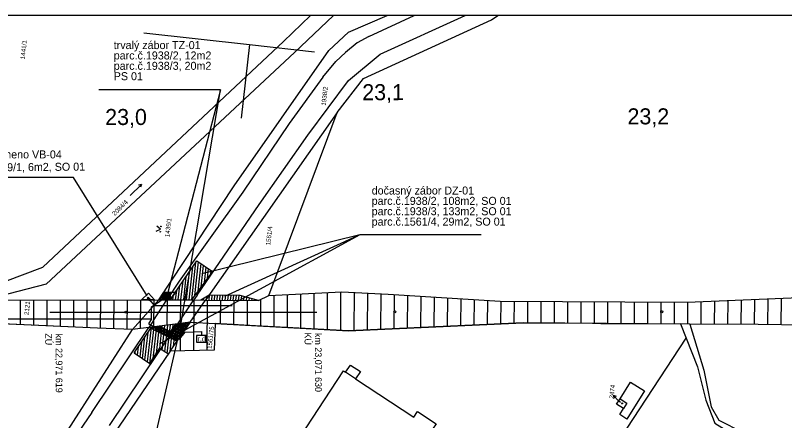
# Model space of a CAD drawing. Extents: x -794765 to -785424, y -1118958 to -1108731.
# Drawn here: x -794556.2 to -794268, y -1110577.7 to -1110426 of the extents above; entities that cross this region are included whole.
import ezdxf

# ---------------------------------------------------------------- set-up
doc = ezdxf.new("R2010")
doc.units = 0
for name, color, linetype in [('Level 66', 7, 'Continuous'), ('Level 71', 7, 'Continuous'), ('Level 73', 7, 'Continuous'), ('Level 75', 7, 'Continuous'), ('Level 76', 7, 'Continuous'), ('Level 77', 7, 'Continuous'), ('Level 78', 7, 'Continuous'), ('Level 79', 7, 'Continuous'), ('Level 80', 7, 'Continuous'), ('Vrstva 1', 7, 'Continuous'), ('Vrstva 53', 7, 'Continuous')]:
    doc.layers.add(name, color=color, linetype=linetype)

msp = doc.modelspace()

# ---------------------------------------------------------------- linework, layer by layer
at = {"layer": 'Level 66'}
for p, q in [((-794513.23, -1110493.46), (-794508.96, -1110489.25)), ((-794508.96, -1110489.25), (-794510.01, -1110489.58)), ((-794508.96, -1110489.25), (-794509.31, -1110490.29))]:
    msp.add_line(p, q, dxfattribs=at)
msp.add_lwpolyline([(-794503.38, -1110506.83), (-794501.77, -1110506), (-794503.15, -1110504.84)], dxfattribs=at)
for centre in [(-794501.66, -1110505.01), (-794501.88, -1110507)]:
    msp.add_circle(centre, 0.1, dxfattribs=at)
at = {"layer": 'Level 71'}
msp.add_line((-793863.95, -1110425.97), (-794764.72, -1110425.97), dxfattribs=at)
at = {"layer": 'Level 75'}
for p, q in [((-794435.64, -1110462.33), (-794484.92, -1110532.56)), ((-794461.25, -1110530.91), (-794435.64, -1110462.33)), ((-794563.75, -1110532.65), (-794502.43, -1110532.44)), ((-794502.43, -1110532.44), (-794499.4, -1110532.46)), ((-794499.4, -1110532.46), (-794489.27, -1110532.53)), ((-794490.73, -1110540.85), (-794484.92, -1110532.56)), ((-794489.27, -1110532.53), (-794484.92, -1110532.56)), ((-794498.16, -1110551.76), (-794490.73, -1110540.85)), ((-794490.73, -1110540.85), (-794495.27, -1110541.44)), ((-794490.73, -1110540.85), (-794481.35, -1110541.37)), ((-794506.24, -1110542.85), (-794512.24, -1110543.62)), ((-794495.27, -1110541.44), (-794506.24, -1110542.85)), ((-794307, -1110541.53), (-794304.9, -1110546.83)), ((-794303.51, -1110541.56), (-794307, -1110541.53)), ((-794382.83, -1110665.46), (-794304.9, -1110546.83))]:
    msp.add_line(p, q, dxfattribs=at)
for points in [[(-794569.05, -1110532.66), (-794566.83, -1110528.14), (-794545.92, -1110520.3), (-794455.77, -1110435.78), (-794445.68, -1110425.97)], [(-794437.06, -1110425.97), (-794451.66, -1110439.85), (-794544.58, -1110526.66), (-794562.65, -1110531.19), (-794563.75, -1110532.65)], [(-794438.77, -1110439.12), (-794431.4, -1110432.22), (-794416.91, -1110425.97)], [(-794435.64, -1110462.33), (-794425.72, -1110449.58), (-794377.85, -1110427.65), (-794375.39, -1110425.97)], [(-794502.43, -1110532.44), (-794474.19, -1110489.74), (-794438.77, -1110439.12)], [(-794484.92, -1110532.56), (-794465.05, -1110532.71), (-794461.25, -1110530.91)], [(-794461.25, -1110530.91), (-794433.94, -1110529.51), (-794416.47, -1110530.42), (-794374.52, -1110532.93), (-794304.55, -1110533.4), (-794259.63, -1110531.53), (-794179.14, -1110530.95), (-794108.47, -1110532.75), (-794104.14, -1110532.79)], [(-794639.83, -1110726.74), (-794626.42, -1110708.17), (-794618.82, -1110702.4), (-794541.78, -1110589.48), (-794512.24, -1110543.62)], [(-794512.24, -1110543.62), (-794525.37, -1110543.07), (-794563.98, -1110541.29), (-794564.28, -1110541.29)], [(-794481.35, -1110541.37), (-794481.77, -1110551.37), (-794498.16, -1110551.76)], [(-794481.35, -1110541.37), (-794431.43, -1110544.09), (-794365.92, -1110541.06), (-794340, -1110541.27), (-794336.92, -1110541.29), (-794307, -1110541.53)], [(-794103.63, -1110542.16), (-794108.46, -1110542.18), (-794182.02, -1110543.07), (-794277.92, -1110541.77), (-794303.51, -1110541.56)], [(-794303.51, -1110541.56), (-794298.33, -1110558.86), (-794295.52, -1110572.59), (-794292.66, -1110577.57), (-794283.75, -1110582), (-794250.19, -1110588.78), (-794232.47, -1110589.11), (-794190.29, -1110595.64), (-794168.42, -1110600.62), (-794159.77, -1110604.9)], [(-794304.9, -1110546.83), (-794300.65, -1110557.55), (-794297.56, -1110570.01), (-794294.21, -1110578.7), (-794285.26, -1110584.18), (-794250.99, -1110590.67), (-794233.64, -1110591.68), (-794191.07, -1110598.44), (-794159.77, -1110604.9)], [(-794498.16, -1110551.76), (-794529.99, -1110598.46), (-794531.8, -1110601.13)], [(-794481.28, -1110658.62), (-794477.38, -1110652.72), (-794489.45, -1110644.78), (-794433.25, -1110559.1), (-794432.45, -1110559.62), (-794430.68, -1110556.89), (-794426.92, -1110559.28), (-794428.75, -1110562.06), (-794406.87, -1110576.43), (-794405.48, -1110574.3), (-794398.59, -1110578.92), (-794399.94, -1110580.98), (-794360.02, -1110607.21), (-794416.32, -1110692.87), (-794428.4, -1110684.94), (-794432.27, -1110690.83)], [(-794328.37, -1110573.19), (-794330.96, -1110571.57), (-794329.68, -1110569.51), (-794325.79, -1110563.26), (-794320.49, -1110566.59), (-794327.15, -1110577.13), (-794329.76, -1110575.48), (-794328.37, -1110573.19)]]:
    msp.add_lwpolyline(points, dxfattribs=at)
at = {"layer": 'Level 77'}
for p, q in [((-794423.73, -1110433.83), (-794406.83, -1110425.97)), ((-794419.5, -1110440.48), (-794387.65, -1110425.97)), ((-794423.73, -1110433.83), (-794428.14, -1110436.28)), ((-794428.14, -1110436.28), (-794432.53, -1110439.86)), ((-794432.53, -1110439.86), (-794436.19, -1110443.25)), ((-794431.42, -1110450.32), (-794419.5, -1110440.48)), ((-794440.95, -1110449.05), (-794436.19, -1110443.25)), ((-794440.95, -1110449.05), (-794453.58, -1110466.48)), ((-794446.66, -1110470.8), (-794431.42, -1110450.32)), ((-794453.58, -1110466.48), (-794470.96, -1110492.11)), ((-794464.86, -1110496.76), (-794446.66, -1110470.8)), ((-794470.96, -1110492.11), (-794494.86, -1110525.52)), ((-794488.07, -1110530.73), (-794464.86, -1110496.76)), ((-794494.86, -1110525.52), (-794499.4, -1110532.46)), ((-794488.07, -1110530.73), (-794489.27, -1110532.53)), ((-794502.43, -1110532.44), (-794512.24, -1110543.62)), ((-794504.46, -1110540.19), (-794499.4, -1110532.46)), ((-794495.27, -1110541.44), (-794489.27, -1110532.53)), ((-794504.46, -1110540.19), (-794506.24, -1110542.85)), ((-794527.59, -1110574.62), (-794506.24, -1110542.85)), ((-794520.95, -1110579.5), (-794496.39, -1110543.1)), ((-794496.39, -1110543.1), (-794495.27, -1110541.44)), ((-794428.75, -1110562.06), (-794432.45, -1110559.62)), ((-794329.68, -1110569.51), (-794327.09, -1110571.12)), ((-794327.09, -1110571.12), (-794328.37, -1110573.19)), ((-794527.59, -1110574.62), (-794548, -1110604.53))]:
    msp.add_line(p, q, dxfattribs=at)
at = {"layer": 'Level 78'}
for p, q in [((-794459.29, -1110542.56), (-794459.21, -1110530.81)), ((-794454.29, -1110542.84), (-794454.21, -1110530.55)), ((-794449.29, -1110543.11), (-794449.2, -1110530.29)), ((-794444.29, -1110543.38), (-794444.2, -1110530.04)), ((-794439.29, -1110543.66), (-794439.2, -1110529.78)), ((-794434.29, -1110543.93), (-794434.2, -1110529.52)), ((-794429.29, -1110543.99), (-794429.2, -1110529.76)), ((-794424.29, -1110543.76), (-794424.2, -1110530.02)), ((-794419.29, -1110543.53), (-794419.2, -1110530.28)), ((-794414.29, -1110543.3), (-794414.21, -1110530.56)), ((-794409.29, -1110543.06), (-794409.21, -1110530.86)), ((-794404.29, -1110542.83), (-794404.21, -1110531.16)), ((-794399.28, -1110542.6), (-794399.21, -1110531.45)), ((-794394.28, -1110542.37), (-794394.21, -1110531.75)), ((-794389.28, -1110542.14), (-794389.21, -1110532.05)), ((-794274.28, -1110541.82), (-794274.21, -1110532.14)), ((-794269.28, -1110541.89), (-794269.21, -1110531.93)), ((-794554.28, -1110541.74), (-794554.22, -1110532.62)), ((-794549.28, -1110541.97), (-794549.22, -1110532.6)), ((-794544.28, -1110542.2), (-794544.22, -1110532.58)), ((-794539.29, -1110542.43), (-794539.22, -1110532.57)), ((-794534.29, -1110542.66), (-794534.22, -1110532.55)), ((-794529.29, -1110542.89), (-794529.22, -1110532.53)), ((-794524.29, -1110543.11), (-794524.22, -1110532.51)), ((-794519.29, -1110543.32), (-794519.22, -1110532.5)), ((-794514.29, -1110543.53), (-794514.22, -1110532.48)), ((-794509.29, -1110543.24), (-794509.22, -1110532.46)), ((-794504.29, -1110542.6), (-794504.22, -1110532.44)), ((-794499.28, -1110541.96), (-794499.22, -1110532.46)), ((-794494.28, -1110541.31), (-794494.22, -1110532.5)), ((-794489.35, -1110551.55), (-794489.22, -1110532.53)), ((-794484.34, -1110551.43), (-794484.22, -1110532.57)), ((-794479.28, -1110541.48), (-794479.22, -1110532.61)), ((-794474.28, -1110541.75), (-794474.22, -1110532.64)), ((-794469.28, -1110542.02), (-794469.22, -1110532.68)), ((-794464.28, -1110542.29), (-794464.22, -1110532.32)), ((-794384.28, -1110541.91), (-794384.22, -1110532.35)), ((-794379.28, -1110541.68), (-794379.22, -1110532.65)), ((-794374.28, -1110541.45), (-794374.22, -1110532.93)), ((-794369.27, -1110541.22), (-794369.22, -1110532.96)), ((-794364.27, -1110541.08), (-794364.22, -1110533)), ((-794359.27, -1110541.12), (-794359.22, -1110533.03)), ((-794354.27, -1110541.16), (-794354.22, -1110533.07)), ((-794349.27, -1110541.2), (-794349.22, -1110533.1)), ((-794344.27, -1110541.23), (-794344.22, -1110533.13)), ((-794339.27, -1110541.27), (-794339.22, -1110533.17)), ((-794334.27, -1110541.31), (-794334.22, -1110533.2)), ((-794329.27, -1110541.35), (-794329.22, -1110533.23)), ((-794324.27, -1110541.39), (-794324.22, -1110533.27)), ((-794319.28, -1110541.43), (-794319.22, -1110533.3)), ((-794314.28, -1110541.47), (-794314.22, -1110533.34)), ((-794309.28, -1110541.51), (-794309.22, -1110533.37)), ((-794304.28, -1110541.55), (-794304.22, -1110533.39)), ((-794299.28, -1110541.59), (-794299.22, -1110533.18)), ((-794294.28, -1110541.63), (-794294.22, -1110532.97)), ((-794289.28, -1110541.68), (-794289.22, -1110532.76)), ((-794284.28, -1110541.72), (-794284.22, -1110532.55)), ((-794279.28, -1110541.76), (-794279.21, -1110532.34)), ((-794494.35, -1110551.67), (-794494.31, -1110546.11))]:
    msp.add_line(p, q, dxfattribs=at)
at = {"layer": 'Level 79'}
msp.add_circle((-794328.92, -1110571.29), 0.175, dxfattribs=at)
at = {"layer": 'Level 80'}
for p, q in [((-794330.11, -1110570.38), (-794332.22, -1110568.24)), ((-794332.22, -1110568.24), (-794331.16, -1110568.61)), ((-794332.22, -1110568.24), (-794331.87, -1110569.31)), ((-794329.53, -1110570.98), (-794330.11, -1110570.38))]:
    msp.add_line(p, q, dxfattribs=at)
at = {"layer": 'Vrstva 1'}
for p, q in [((-794508.04, -1110432.46), (-794468.5, -1110436.88)), ((-794468.5, -1110436.88), (-794471.59, -1110464.49)), ((-794468.5, -1110436.88), (-794444.13, -1110439.6)), ((-794479.37, -1110453.88), (-794524.86, -1110453.88)), ((-794479.37, -1110453.88), (-794499.23, -1110530.2)), ((-794494.38, -1110542.53), (-794479.37, -1110453.88)), ((-794534.44, -1110486.62), (-794579.93, -1110486.62)), ((-794427.16, -1110508.13), (-794502.31, -1110549.13)), ((-794427.16, -1110508.13), (-794486.33, -1110522.74)), ((-794427.16, -1110508.13), (-794477.86, -1110531.23)), ((-794381.68, -1110508.13), (-794427.16, -1110508.13)), ((-794498.16, -1110532.47), (-794488.19, -1110517.86)), ((-794488.19, -1110517.86), (-794482.34, -1110521.82)), ((-794491.12, -1110532.52), (-794489.74, -1110520.12)), ((-794490.11, -1110532.49), (-794488.54, -1110518.36)), ((-794488.93, -1110530.86), (-794487.52, -1110518.31)), ((-794487.74, -1110529.23), (-794486.59, -1110518.94)), ((-794486.55, -1110527.6), (-794485.65, -1110519.58)), ((-794485.36, -1110525.97), (-794484.72, -1110520.21)), ((-794492.13, -1110532.51), (-794490.94, -1110521.89)), ((-794482.34, -1110521.82), (-794490.14, -1110532.52)), ((-794484.17, -1110524.34), (-794483.78, -1110520.84)), ((-794482.98, -1110522.71), (-794482.85, -1110521.48)), ((-794494.14, -1110532.49), (-794493.35, -1110525.41)), ((-794493.13, -1110532.5), (-794492.15, -1110523.65)), ((-794496.15, -1110532.48), (-794495.75, -1110528.93)), ((-794495.15, -1110532.49), (-794494.55, -1110527.17)), ((-794506.33, -1110530.03), (-794508.88, -1110532.46)), ((-794506.37, -1110531.45), (-794506.84, -1110531.9)), ((-794506.37, -1110531.45), (-794506.84, -1110531.9)), ((-794506.84, -1110531.9), (-794506.02, -1110532.77)), ((-794506.84, -1110531.9), (-794506.02, -1110532.77)), ((-794506.74, -1110531.8), (-794506.05, -1110532.52)), ((-794506.74, -1110531.8), (-794506.05, -1110532.52)), ((-794505.79, -1110532.27), (-794506.48, -1110531.55)), ((-794506.48, -1110531.55), (-794505.79, -1110532.27)), ((-794505.54, -1110532.32), (-794506.37, -1110531.45)), ((-794506.37, -1110531.45), (-794505.54, -1110532.32)), ((-794504.03, -1110532.44), (-794506.33, -1110530.03)), ((-794505.15, -1110535.12), (-794498.51, -1110530.57)), ((-794502.23, -1110532.44), (-794502.19, -1110532.07)), ((-794501.73, -1110532.44), (-794501.59, -1110531.16)), ((-794501.23, -1110532.45), (-794500.98, -1110530.24)), ((-794500.73, -1110532.45), (-794500.4, -1110529.56)), ((-794500.22, -1110532.45), (-794499.9, -1110529.56)), ((-794499.72, -1110532.46), (-794499.4, -1110529.56)), ((-794499.22, -1110532.46), (-794498.89, -1110529.57)), ((-794498.71, -1110532.46), (-794498.39, -1110529.57)), ((-794498.21, -1110532.47), (-794497.89, -1110529.57)), ((-794497.16, -1110532.47), (-794496.96, -1110530.7)), ((-794483.58, -1110530.73), (-794486.65, -1110532.55)), ((-794485.65, -1110532.56), (-794485.58, -1110531.91)), ((-794484.64, -1110532.57), (-794484.5, -1110531.28)), ((-794483.64, -1110532.57), (-794483.43, -1110530.74)), ((-794471.94, -1110530.85), (-794483.58, -1110530.73)), ((-794482.63, -1110532.58), (-794482.43, -1110530.75)), ((-794481.63, -1110532.59), (-794481.42, -1110530.76)), ((-794480.62, -1110532.6), (-794480.42, -1110530.76)), ((-794479.62, -1110532.6), (-794479.41, -1110530.77)), ((-794478.61, -1110532.61), (-794478.41, -1110530.78)), ((-794477.61, -1110532.62), (-794477.4, -1110530.79)), ((-794476.6, -1110532.63), (-794476.4, -1110530.8)), ((-794475.6, -1110532.63), (-794475.39, -1110530.81)), ((-794474.59, -1110532.64), (-794474.39, -1110530.82)), ((-794473.58, -1110532.65), (-794473.38, -1110530.83)), ((-794472.58, -1110532.66), (-794472.38, -1110530.84)), ((-794465.05, -1110532.71), (-794471.94, -1110530.85)), ((-794471.57, -1110532.66), (-794471.39, -1110531)), ((-794470.57, -1110532.67), (-794470.41, -1110531.26)), ((-794469.56, -1110532.68), (-794469.43, -1110531.53)), ((-794468.56, -1110532.69), (-794468.46, -1110531.79)), ((-794467.55, -1110532.69), (-794467.48, -1110532.05)), ((-794507.21, -1110532.46), (-794507.21, -1110532.46)), ((-794506.05, -1110532.52), (-794505.79, -1110532.27)), ((-794506.05, -1110532.52), (-794505.79, -1110532.27)), ((-794506.02, -1110532.77), (-794505.54, -1110532.32)), ((-794506.02, -1110532.77), (-794505.54, -1110532.32)), ((-794503.88, -1110534.71), (-794505.78, -1110532.54)), ((-794505.18, -1110539.61), (-794505.15, -1110535.12)), ((-794475.02, -1110534.68), (-794503.88, -1110534.71)), ((-794502.43, -1110532.44), (-794499.4, -1110532.46)), ((-794466.55, -1110532.7), (-794466.5, -1110532.32)), ((-794465.54, -1110532.71), (-794465.53, -1110532.58)), ((-794575.12, -1110539.63), (-794527.51, -1110539.57)), ((-794527.51, -1110539.57), (-794505.18, -1110539.61)), ((-794505.18, -1110539.61), (-794506.34, -1110541.45)), ((-794490.73, -1110540.85), (-794495.27, -1110541.44)), ((-794491.23, -1110541.59), (-794491.16, -1110540.91)), ((-794511.66, -1110552.33), (-794505.19, -1110542.72)), ((-794506.68, -1110555.72), (-794505.24, -1110542.78)), ((-794506.34, -1110541.45), (-794497.72, -1110545.73)), ((-794505.97, -1110542.81), (-794495.54, -1110547.91)), ((-794505.75, -1110556.35), (-794504.21, -1110542.59)), ((-794505.56, -1110543.01), (-794505.53, -1110542.75)), ((-794505.08, -1110543.24), (-794505.02, -1110542.69)), ((-794504.6, -1110543.48), (-794504.51, -1110542.62)), ((-794504.53, -1110554.46), (-794503.19, -1110542.46)), ((-794504.13, -1110543.71), (-794504, -1110542.56)), ((-794503.65, -1110543.94), (-794503.49, -1110542.49)), ((-794503.31, -1110552.56), (-794502.17, -1110542.33)), ((-794503.17, -1110544.18), (-794502.98, -1110542.43)), ((-794502.7, -1110544.41), (-794502.47, -1110542.36)), ((-794502.36, -1110542.35), (-794498.09, -1110544.43)), ((-794502.22, -1110544.64), (-794501.98, -1110542.53)), ((-794502.1, -1110550.75), (-794501.15, -1110542.2)), ((-794501.74, -1110544.88), (-794501.51, -1110542.77)), ((-794501.26, -1110545.11), (-794501.03, -1110543)), ((-794501.16, -1110551.34), (-794500.13, -1110542.07)), ((-794500.79, -1110545.34), (-794500.55, -1110543.23)), ((-794500.31, -1110545.58), (-794500.07, -1110543.47)), ((-794500.22, -1110551.94), (-794499.11, -1110541.94)), ((-794499.83, -1110545.81), (-794499.6, -1110543.7)), ((-794499.28, -1110552.53), (-794498.08, -1110541.81)), ((-794496.05, -1110541.54), (-794498.09, -1110544.43)), ((-794497.72, -1110545.73), (-794496.01, -1110543.22)), ((-794497.61, -1110544.67), (-794497.49, -1110543.59)), ((-794497.24, -1110543.23), (-794497.06, -1110541.67)), ((-794497.14, -1110544.9), (-794496.89, -1110542.74)), ((-794496.66, -1110545.13), (-794496.3, -1110541.9)), ((-794496.18, -1110545.37), (-794495.75, -1110541.51)), ((-794495.7, -1110545.6), (-794495.24, -1110541.44)), ((-794495.23, -1110545.83), (-794494.73, -1110541.37)), ((-794494.75, -1110546.06), (-794494.22, -1110541.31)), ((-794494.24, -1110546.01), (-794493.71, -1110541.24)), ((-794493.64, -1110545.12), (-794493.2, -1110541.17)), ((-794493.04, -1110544.24), (-794492.69, -1110541.11)), ((-794492.44, -1110543.36), (-794492.18, -1110541.04)), ((-794491.83, -1110542.48), (-794491.67, -1110540.97)), ((-794508.55, -1110554.44), (-794507.65, -1110546.37)), ((-794507.62, -1110555.08), (-794506.44, -1110544.58)), ((-794499.36, -1110546.04), (-794499.12, -1110543.93)), ((-794498.88, -1110546.28), (-794498.64, -1110544.16)), ((-794498.4, -1110546.51), (-794498.17, -1110544.4)), ((-794498.2, -1110551.81), (-794497.41, -1110544.77)), ((-794498.09, -1110544.43), (-794494.4, -1110546.24)), ((-794498.09, -1110544.43), (-794498.09, -1110544.43)), ((-794497.93, -1110546.74), (-794497.69, -1110544.63)), ((-794497.72, -1110545.73), (-794494.75, -1110547.18)), ((-794497.45, -1110546.98), (-794497.21, -1110544.86)), ((-794496.99, -1110550.05), (-794496.45, -1110545.23)), ((-794496.97, -1110547.21), (-794496.73, -1110545.1)), ((-794496.49, -1110547.44), (-794496.26, -1110545.33)), ((-794496.02, -1110547.68), (-794495.78, -1110545.56)), ((-794495.79, -1110548.28), (-794495.5, -1110545.7)), ((-794495.54, -1110547.91), (-794495.3, -1110545.79)), ((-794494.94, -1110547.03), (-794494.83, -1110546.03)), ((-794494.75, -1110547.18), (-794492.53, -1110544.65)), ((-794494.59, -1110546.51), (-794494.55, -1110546.16)), ((-794492.53, -1110544.65), (-794486.51, -1110544.37)), ((-794484.71, -1110545.84), (-794488.31, -1110545.85)), ((-794488.31, -1110545.85), (-794488.31, -1110548.36)), ((-794486.51, -1110544.37), (-794486.51, -1110545.85)), ((-794484.71, -1110548.34), (-794484.71, -1110545.84)), ((-794509.49, -1110553.81), (-794508.86, -1110548.17)), ((-794506.01, -1110593.59), (-794495.26, -1110547.22)), ((-794488.31, -1110548.36), (-794484.71, -1110548.34)), ((-794511.66, -1110552.33), (-794505.75, -1110556.35)), ((-794511.36, -1110552.53), (-794511.27, -1110551.76)), ((-794510.42, -1110553.17), (-794510.06, -1110549.96)), ((-794505.75, -1110556.35), (-794502.13, -1110550.73)), ((-794498.87, -1110552.79), (-794502.13, -1110550.73)), ((-794498.16, -1110551.76), (-794498.16, -1110551.76))]:
    msp.add_line(p, q, dxfattribs=at)
for points in [[(-794506.86, -1110530.99), (-794534.44, -1110486.62)], [(-794543.21, -1110537.14), (-794522.01, -1110537.12), (-794518.01, -1110537.12), (-794502.41, -1110537.1), (-794491.62, -1110537.1), (-794443.19, -1110537.05)]]:
    msp.add_lwpolyline(points, dxfattribs=at)
for points in [[(-794508.88, -1110532.46), (-794506.33, -1110530.03), (-794504.03, -1110532.44)], [(-794502.43, -1110532.44), (-794500.53, -1110529.56), (-794496.2, -1110529.58), (-794498.16, -1110532.47), (-794499.4, -1110532.46)], [(-794498.09, -1110544.43), (-794496.05, -1110541.54), (-794495.27, -1110541.44), (-794490.73, -1110540.85), (-794494.4, -1110546.24)], [(-794505.97, -1110542.81), (-794495.54, -1110547.91), (-794494.4, -1110546.24), (-794498.09, -1110544.43), (-794502.36, -1110542.35)]]:
    msp.add_lwpolyline(points, close=True, dxfattribs=at)
for centre in [(-794514.82, -1110537.12), (-794414.07, -1110537.02), (-794314.07, -1110536.93)]:
    msp.add_circle(centre, 0.375, dxfattribs=at)
at = {"layer": 'Vrstva 53'}
for points in [[(-794502.43, -1110532.44), (-794489.27, -1110532.53), (-794484.92, -1110532.56), (-794465.05, -1110532.71), (-794461.25, -1110530.91), (-794433.94, -1110529.51), (-794416.47, -1110530.42), (-794374.52, -1110532.93), (-794304.55, -1110533.4), (-794259.63, -1110531.53), (-794179.14, -1110530.95), (-794108.47, -1110532.75), (-794084.53, -1110532.8), (-794010.09, -1110532.85), (-793996.56, -1110532.76), (-793981.76, -1110532.68), (-793975.51, -1110532.65), (-793967.39, -1110532.61), (-793910.94, -1110532.3), (-793878.1, -1110531.77), (-793873.87, -1110531.7), (-793863.95, -1110531.55)], [(-794525.37, -1110543.07), (-794564.28, -1110541.29), (-794564.28, -1110541.29), (-794564.17, -1110539.4), (-794565.51, -1110539.39), (-794565.52, -1110535.1), (-794563.9, -1110535.12), (-794563.75, -1110532.65), (-794502.43, -1110532.44)], [(-793863.95, -1110540.92), (-793872.21, -1110540.79), (-793877.49, -1110541.02), (-793973.24, -1110541.53), (-793978.2, -1110541.55), (-793980.91, -1110541.57), (-793989.37, -1110541.63), (-794005.25, -1110541.75), (-794103.63, -1110542.16), (-794108.46, -1110542.18), (-794182.02, -1110543.07), (-794277.92, -1110541.77), (-794303.51, -1110541.56), (-794365.92, -1110541.06), (-794431.43, -1110544.09), (-794466.19, -1110542.18), (-794481.35, -1110541.37), (-794481.77, -1110551.37), (-794498.16, -1110551.76), (-794490.73, -1110540.85), (-794495.27, -1110541.44), (-794506.24, -1110542.85), (-794512.24, -1110543.62), (-794525.37, -1110543.07)]]:
    msp.add_lwpolyline(points, dxfattribs=at)

# ---------------------------------------------------------------- texts
at = {"layer": 'Level 73'}
for s, rotation, p in [('23,1', 0.06, (-794426.23, -1110457.73)), ('23,0', 0.0416, (-794522.53, -1110467.02)), ('23,2', 0.0104, (-794326.88, -1110466.78))]:
    msp.add_text(s, height=6, rotation=rotation, dxfattribs=at).set_placement(p)
at = {"layer": 'Level 76'}
for s, rotation, p in [('1441/1', 83.6237, (-794552.65, -1110442.48)), ('1938/2', 83.6237, (-794439.91, -1110459.85)), ('2084/4', 44.6237, (-794518.94, -1110501.13)), ('1439/1', 83.6237, (-794498.49, -1110509.1)), ('1561/4', 83.6237, (-794460.71, -1110512.19)), ('2121', 83.6237, (-794551.22, -1110538.29)), ('1561/75', 83.6237, (-794482.66, -1110550.94)), ('2474', 83.6237, (-794332.09, -1110569.58))]:
    msp.add_text(s, height=1.7, rotation=rotation, dxfattribs=at).set_placement(p)
at = {"layer": 'Vrstva 1'}
for s, height, p in [('trvalý zábor TZ-01', 3, (-794519.33, -1110438.59)), ('parc.č.1938/2, 12m2', 3, (-794519.33, -1110442.47)), ('parc.č.1938/3, 20m2', 3, (-794519.33, -1110446.35)), ('PS 01', 3, (-794519.33, -1110450.24)), ('věcné břemeno VB-04', 3, (-794578.71, -1110479.53)), ('dočasný zábor DZ-01', 3, (-794422.7, -1110493.05)), ('parc.č.1938/2, 108m2, SO 01', 3, (-794422.7, -1110496.93)), ('parc.č.1938/3, 133m2, SO 01', 3, (-794422.7, -1110500.81)), ('parc.č.1561/4, 29m2, SO 01', 3, (-794422.7, -1110504.7)), ('r.d.', 2, (-794488, -1110548.05))]:
    msp.add_text(s, height=height, dxfattribs=at).set_placement(p)
for s, height, rotation, p in [('parc.č.1439/1, 6m2, SO 01', 3, 0.4655, (-794577.99, -1110484.48)), ('ZÚ', 2.5, 269.6886, (-794544.97, -1110545.01)), ('km 22,971 619', 2.5, 270.0496, (-794541.05, -1110545.16)), ('KÚ', 2.5, 269.6886, (-794447.83, -1110544.72)), ('km 23,071 630', 2.5, 270.0496, (-794443.95, -1110544.88))]:
    msp.add_text(s, height=height, rotation=rotation, dxfattribs=at).set_placement(p)

doc.saveas('drawing.dxf')
